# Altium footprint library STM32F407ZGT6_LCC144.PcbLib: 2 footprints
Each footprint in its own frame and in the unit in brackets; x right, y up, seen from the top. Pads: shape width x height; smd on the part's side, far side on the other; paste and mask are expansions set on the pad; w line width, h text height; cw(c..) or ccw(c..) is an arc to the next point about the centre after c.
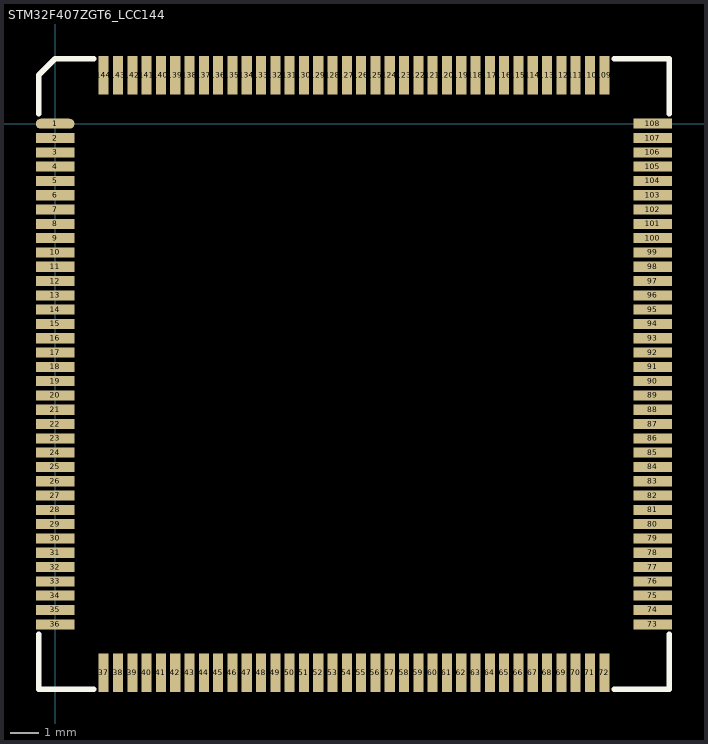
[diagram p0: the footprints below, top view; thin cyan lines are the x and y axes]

## PCBComponent_1 [mm]

## STM32F407ZGT6_LCC144 [mm]
pads (144):
  oval 1.35x0.35 smd: 1(0,0)
  rect 1.35x0.35 smd: 2(0,-0.5) 3(0,-1) 4(0,-1.5) 5(0,-2) 6(0,-2.5) 7(0,-3) 8(0,-3.5) 9(0,-4) 10(0,-4.5) 11(0,-5) 12(0,-5.5) 13(0,-6) 14(0,-6.5) 15(0,-7) 16(0,-7.5) 17(0,-8) 18(0,-8.5) 19(0,-9) 20(0,-9.5) 21(0,-10) 22(0,-10.5) 23(0,-11) 24(0,-11.5) 25(0,-12) 26(0,-12.5) 27(0,-13) 28(0,-13.5) 29(0,-14) 30(0,-14.5) 31(0,-15) 32(0,-15.5) 33(0,-16) 34(0,-16.5) 35(0,-17) 36(0,-17.5) 73(20.9,-17.5) 74(20.9,-17) 75(20.9,-16.5) 76(20.9,-16) 77(20.9,-15.5) 78(20.9,-15) 79(20.9,-14.5) 80(20.9,-14) 81(20.9,-13.5) 82(20.9,-13) 83(20.9,-12.5) 84(20.9,-12) 85(20.9,-11.5) 86(20.9,-11) 87(20.9,-10.5) 88(20.9,-10) 89(20.9,-9.5) 90(20.9,-9) 91(20.9,-8.5) 92(20.9,-8) 93(20.9,-7.5) 94(20.9,-7) 95(20.9,-6.5) 96(20.9,-6) 97(20.9,-5.5) 98(20.9,-5) 99(20.9,-4.5) 100(20.9,-4) 101(20.9,-3.5) 102(20.9,-3) 103(20.9,-2.5) 104(20.9,-2) 105(20.9,-1.5) 106(20.9,-1) 107(20.9,-0.5) 108(20.9,0)
  rect 0.35x1.35 smd: 37(1.7,-19.2) 38(2.2,-19.2) 39(2.7,-19.2) 40(3.2,-19.2) 41(3.7,-19.2) 42(4.2,-19.2) 43(4.7,-19.2) 44(5.2,-19.2) 45(5.7,-19.2) 46(6.2,-19.2) 47(6.7,-19.2) 48(7.2,-19.2) 49(7.7,-19.2) 50(8.2,-19.2) 51(8.7,-19.2) 52(9.2,-19.2) 53(9.7,-19.2) 54(10.2,-19.2) 55(10.7,-19.2) 56(11.2,-19.2) 57(11.7,-19.2) 58(12.2,-19.2) 59(12.7,-19.2) 60(13.2,-19.2) 61(13.7,-19.2) 62(14.2,-19.2) 63(14.7,-19.2) 64(15.2,-19.2) 65(15.7,-19.2) 66(16.2,-19.2) 67(16.7,-19.2) 68(17.2,-19.2) 69(17.7,-19.2) 70(18.2,-19.2) 71(18.7,-19.2) 72(19.2,-19.2) 109(19.2,1.7) 110(18.7,1.7) 111(18.2,1.7) 112(17.7,1.7) 113(17.2,1.7) 114(16.7,1.7) 115(16.2,1.7) 116(15.7,1.7) 117(15.2,1.7) 118(14.7,1.7) 119(14.2,1.7) 120(13.7,1.7) 121(13.2,1.7) 122(12.7,1.7) 123(12.2,1.7) 124(11.7,1.7) 125(11.2,1.7) 126(10.7,1.7) 127(10.2,1.7) 128(9.7,1.7) 129(9.2,1.7) 130(8.7,1.7) 131(8.2,1.7) 132(7.7,1.7) 133(7.2,1.7) 134(6.7,1.7) 135(6.2,1.7) 136(5.7,1.7) 137(5.2,1.7) 138(4.7,1.7) 139(4.2,1.7) 140(3.7,1.7) 141(3.2,1.7) 142(2.7,1.7) 143(2.2,1.7) 144(1.7,1.7)
Top Overlay:
  lines w0.2: -0.575,-17.85 -0.575,-19.775 1.35,-19.775 ; -0.575,0.35 -0.575,1.7 0,2.275 1.35,2.275 ; 19.55,-19.775 21.475,-19.775 21.475,-17.85 ; 19.55,2.275 21.475,2.275 21.475,0.35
